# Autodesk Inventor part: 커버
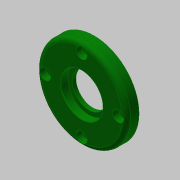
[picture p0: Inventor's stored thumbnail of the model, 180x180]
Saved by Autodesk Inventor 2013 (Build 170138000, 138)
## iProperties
Created: 2019-09
Part Number: 커버
Material: 일반
Document SubType Name: Modeling
Designer: mduedu
Density: 1 g/cm^3
Author: mduedu
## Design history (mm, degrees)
sketch "스케치1"
  geometry: C1 r 32 at (0, 0); 1 further point
  constraints: 1 centre point, 1 coincident
  dimensions: "d0" = 64 diameter of C1
extrude "돌출1" new body sketch "스케치1" distance "d1" = 9; taper "d2" = 0 deg
sketch "스케치2"
  geometry: C1 r 21 at (0, 0); 1 further point
  constraints: 1 centre point, 1 coincident
  dimensions: "d3" = 42 diameter of C1
extrude "돌출2" join sketch "스케치2" distance "d4" = 3; taper "d5" = 0 deg
hole "구멍1" diameter "d8" = 24; stored, may be unused: countersink angle "d12" = 90 deg, drill point angle "d14" = 118 deg; dims "d6" = 10, "d7" = 10, "d9" = 6, "d10" = 30, "d11" = 5.2, "d13" = 8
hole "구멍2" diameter "d17" = 37; stored, may be unused: countersink angle "d21" = 90 deg, drill point angle "d23" = 0 deg; dims "d15" = 10, "d16" = 10, "d18" = 6, "d19" = 30, "d20" = 5.2, "d22" = 4
fillet "모깎기1" dims "d24" = 3
fillet "모깎기2" dims "d25" = 3
chamfer "모따기1" distance "d27" = 0.5; stored, may be unused: second distance "d28" = 2, angle "d29" = 30 deg
chamfer "모따기2" distance "d30" = 1; stored, may be unused: second distance "d31" = 2, angle "d32" = 30 deg
sketch "스케치3" dims "d33" = 52
  geometry: 3 further points
  constraints: 2 vertical alignment, 1 coincident, 2 other
hole "구멍3" sketch "스케치3" at (0, 26) diameter "d34" = 4.5; stored, may be unused: countersink angle "d38" = 90 deg, drill point angle "d40" = 0 deg; dims "d35" = 6, "d36" = 8, "d37" = 4.4, "d39" = 4
node "솔리드1"
pattern_circular "원형 패턴1" dims angle "d42" = 360 deg
